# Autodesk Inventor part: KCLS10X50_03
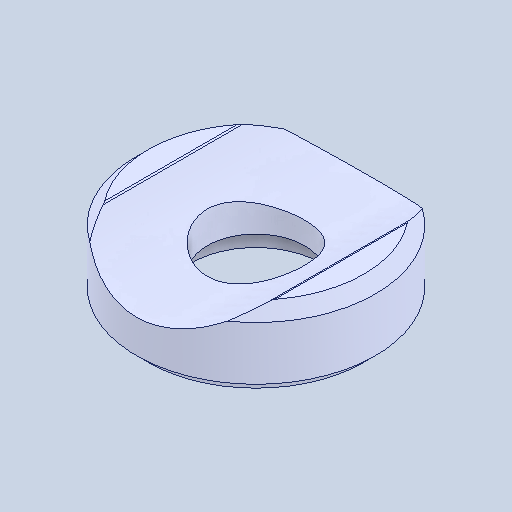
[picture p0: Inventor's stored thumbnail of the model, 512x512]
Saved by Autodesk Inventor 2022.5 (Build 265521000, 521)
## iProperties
Created: 2024-08
Part Number: KCLS10X50_03
Material: 一般
Document SubType Name: Modeling
Designer: ImaoCorp
Density: 1 g/cm^3
Appearance: 既定
Author: ImaoCorp
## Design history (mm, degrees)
feature "KCLS10X50_03"
node "ソリッド1"
